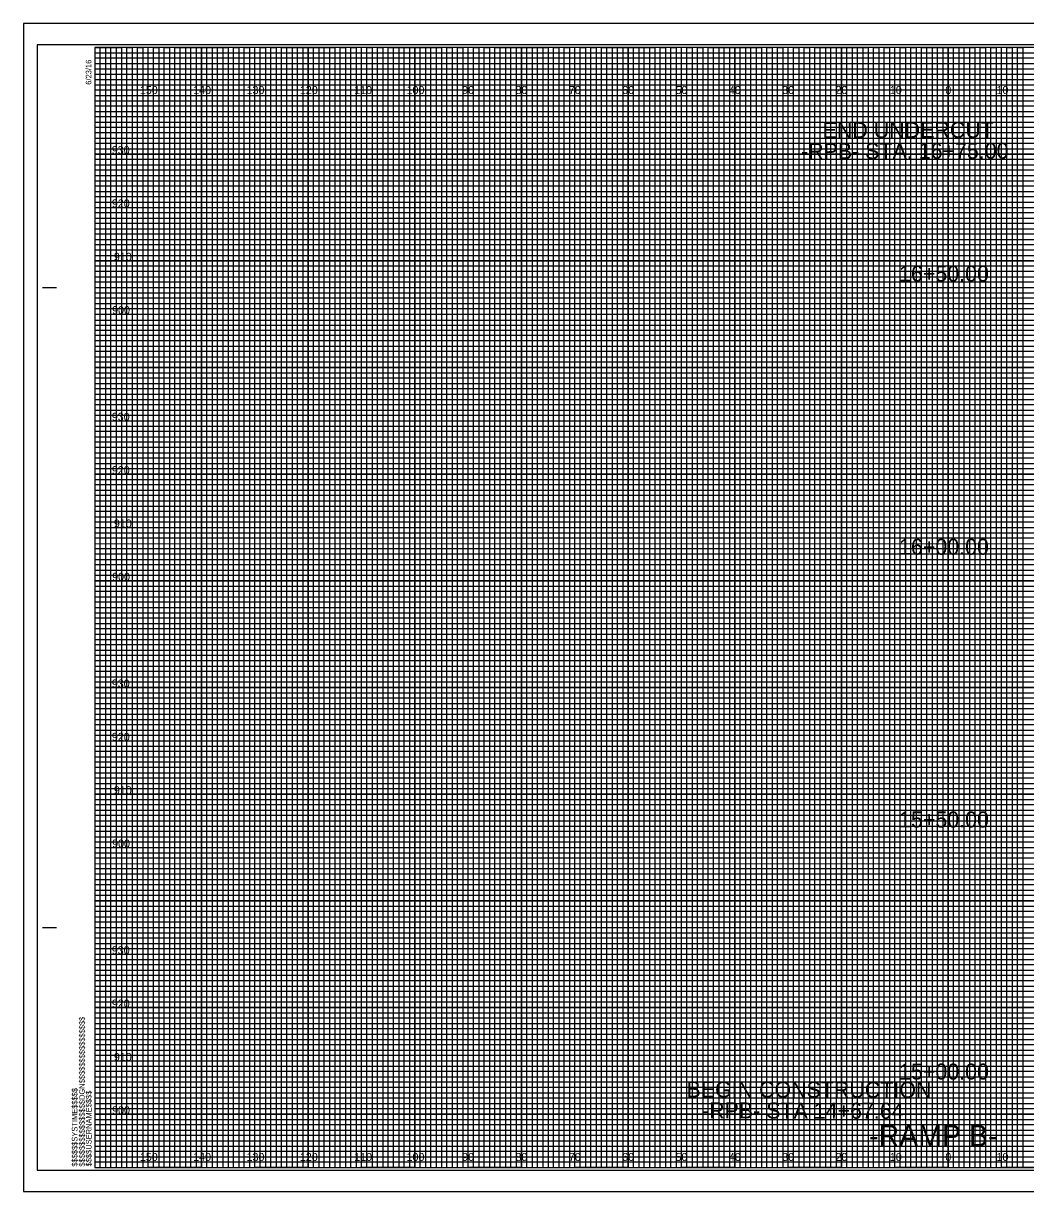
# Model space of a CAD drawing. Extents: x -13 to 323, y -4 to 214.
# Drawn here: x -13.4 to 174.5, y -4.5 to 214.5 of the extents above; entities that cross this region are included whole.
import ezdxf

# ---------------------------------------------------------------- set-up
doc = ezdxf.new("R2010")
doc.units = 0
for name, color, linetype in [('Prop XS Alignment Label', 7, 'Continuous'), ('Prop XS Elevation Labels', 7, 'Continuous'), ('Prop XS Offset Labels', 7, 'Continuous'), ('Prop XS SE Text', 7, 'Continuous'), ('Prop XS Station Labels', 7, 'Continuous'), ('Sheet Cross Section CELL', 7, 'Continuous'), ('Sheet Cross Section Grid Major CELL', 7, 'Continuous'), ('Sheet Cross Section Grid Middle CELL', 7, 'Continuous'), ('Sheet Cross Section Grid Minor 1 CELL', 7, 'Continuous'), ('Sheet Cross Section Grid Minor 2 CELL', 7, 'Continuous'), ('Sheet Cutting Line CELL', 7, 'Continuous'), ('Sheet DOT Grid CELL', 7, 'Continuous'), ('Sheet Plot Border Inside CELL', 7, 'Continuous'), ('Sheet Plot Border Outside CELL', 7, 'Continuous')]:
    doc.layers.add(name, color=color, linetype=linetype)

msp = doc.modelspace()

# ---------------------------------------------------------------- linework, layer by layer
at = {"layer": 'Sheet Cross Section CELL'}
for p, q in [((-9.8, 165), (-7.3, 165)), ((-9.7, 165), (-7.2, 165)), ((-9.8, 45), (-7.3, 45)), ((-9.7, 45), (-7.2, 45)), ((0, 0), (0, 0)), ((0, 0), (0, 0)), ((0, 0), (0, 0)), ((0, 0), (0, 0)), ((0, 0), (0, 0)), ((0, 0), (0, 0)), ((0, 0), (0, 0))]:
    msp.add_line(p, q, dxfattribs=at)
msp.add_lwpolyline([(320, 210), (0, 210), (0, 0), (320, 0)], close=True, dxfattribs=at)
at = {"layer": 'Sheet Cross Section Grid Major CELL'}
for p, q in [((10, 210), (0, 210)), ((10, 0), (10, 210)), ((30, 210), (20, 210)), ((20, 210), (20, 0)), ((30, 0), (30, 210)), ((50, 210), (40, 210)), ((40, 210), (40, 0)), ((50, 0), (50, 210)), ((70, 210), (60, 210)), ((60, 210), (60, 0)), ((70, 0), (70, 210)), ((90, 210), (80, 210)), ((80, 210), (80, 0)), ((90, 0), (90, 210)), ((110, 210), (100, 210)), ((100, 210), (100, 0)), ((110, 0), (110, 210)), ((130, 210), (120, 210)), ((120, 210), (120, 0)), ((130, 0), (130, 210)), ((150, 210), (140, 210)), ((140, 210), (140, 0)), ((150, 0), (150, 210)), ((170, 210), (160, 210)), ((160, 210), (160, 0)), ((170, 0), (170, 210)), ((20, 0), (10, 0)), ((40, 0), (30, 0)), ((60, 0), (50, 0)), ((80, 0), (70, 0)), ((100, 0), (90, 0)), ((120, 0), (110, 0)), ((140, 0), (130, 0)), ((160, 0), (150, 0)), ((180, 0), (170, 0))]:
    msp.add_line(p, q, dxfattribs=at)
for points in [[(0, 200), (320, 200), (320, 190), (0, 190)], [(0, 180), (320, 180), (320, 170), (0, 170)], [(0, 160), (320, 160), (320, 150), (0, 150)], [(0, 140), (320, 140), (320, 130), (0, 130)], [(0, 120), (320, 120), (320, 110), (0, 110)], [(0, 100), (320, 100), (320, 90), (0, 90)], [(0, 80), (320, 80), (320, 70), (0, 70)], [(0, 60), (320, 60), (320, 50), (0, 50)], [(0, 40), (320, 40), (320, 30), (0, 30)], [(0, 20), (320, 20), (320, 10), (0, 10)]]:
    msp.add_lwpolyline(points, dxfattribs=at)
at = {"layer": 'Sheet Cross Section Grid Middle CELL'}
for points in [[(0, 210), (5, 210), (5, 0), (15, 0), (15, 210), (25, 210), (25, 0), (35, 0), (35, 210), (45, 210), (45, 0), (55, 0), (55, 210), (65, 210), (65, 0), (75, 0), (75, 210), (85, 210), (85, 0), (95, 0), (95, 210), (105, 210), (105, 0), (115, 0), (115, 210), (125, 210), (125, 0), (135, 0), (135, 210), (145, 210), (145, 0), (155, 0), (155, 210), (165, 210), (165, 0), (175, 0)], [(0, 205), (275, 205)], [(0, 185), (320, 185), (320, 195), (0, 195)], [(0, 165), (320, 165), (320, 175), (0, 175)], [(0, 145), (320, 145), (320, 155), (0, 155)], [(0, 125), (320, 125), (320, 135), (0, 135)], [(0, 105), (320, 105), (320, 115), (0, 115)], [(0, 85), (320, 85), (320, 95), (0, 95)], [(0, 65), (320, 65), (320, 75), (0, 75)], [(0, 45), (320, 45), (320, 55), (0, 55)], [(0, 25), (320, 25), (320, 35), (0, 35)], [(0, 5), (320, 5), (320, 15), (0, 15)]]:
    msp.add_lwpolyline(points, dxfattribs=at)
at = {"layer": 'Sheet Cross Section Grid Minor 1 CELL'}
for p, q in [((0, 209), (260, 209)), ((260, 207.98), (0, 207.98)), ((0, 207.98), (0, 207)), ((0, 207), (260, 207)), ((260, 205.89), (0, 205.89)), ((0, 205.89), (0, 204)), ((0, 204), (320, 204))]:
    msp.add_line(p, q, dxfattribs=at)
for points in [[(0, 203), (270, 203), (320, 203), (320, 202), (0, 202)], [(0, 201), (320, 201), (320, 199), (0, 199)], [(0, 198), (320, 198), (320, 197), (0, 196.98)], [(0, 196), (320, 196), (320, 194), (0, 194)], [(0, 193), (320, 193), (320, 192), (0, 192)], [(0, 191), (320, 191), (320, 189), (0, 189)], [(0, 188), (320, 188), (320, 187), (0, 187)], [(0, 186), (320, 186), (320, 184), (0, 184)], [(0, 183), (320, 183), (320, 182), (0, 182)], [(0, 181), (320, 181), (320, 179), (0, 179)], [(0, 178), (320, 178), (320, 177), (0, 177)], [(0, 176), (320, 176), (320, 173.95), (320, 173), (320, 172), (0, 172)], [(0, 174), (320, 174), (320, 173), (0, 173)], [(0, 171), (320, 171), (320, 169), (0, 169.03)], [(0, 169.03), (320, 169), (320, 168), (0, 168)], [(0, 167), (320, 167), (320, 166), (0, 166)], [(0, 164), (320, 164), (320, 163), (0, 163)], [(0, 162), (320, 162), (320, 161), (0, 161)], [(-0.07, 158.89), (320, 158.89), (320, 157.88), (-0.07, 157.88)], [(0, 157), (320, 157), (320, 156), (0, 156)], [(0, 154), (320, 154), (320, 153), (0, 153)], [(0, 152), (320, 152), (320, 151), (0, 151)], [(0, 149), (320, 149), (320, 148), (0, 148)], [(0, 147), (320, 147), (320, 146), (0, 146)], [(0, 144), (320, 144), (320, 143), (0, 143)], [(0, 142), (320, 142), (320, 141), (0, 141)], [(0, 139), (320, 139), (319.99, 137.98), (0, 138)], [(0, 137), (320, 137), (320, 136), (0, 136)], [(0, 134), (320, 134), (320, 133), (0, 133)], [(0, 132), (320, 132), (320, 131), (0, 131)], [(0, 129), (320, 129), (320, 128), (0, 128)], [(0, 127), (320, 127), (320, 126), (0, 126)], [(0, 124), (320, 124), (320, 123), (0, 123)], [(0, 122), (320, 122), (320, 121), (0, 121)], [(0, 119), (320, 119), (320, 118), (0, 118)], [(0, 116.99), (320.07, 116.91), (320, 116), (0, 116)], [(0, 114), (320, 114), (320, 113), (0, 113)], [(0, 112), (320, 112), (320, 111), (0, 111)], [(0, 109), (320, 109), (320, 108), (0, 108)], [(0, 107), (320, 107), (320, 106), (0, 106)], [(0, 104), (320, 104), (320, 103), (0, 103)], [(0, 102), (320, 102), (320, 101), (0, 101)], [(0, 99), (320, 99), (320, 98), (0, 98)], [(0, 97), (320, 97), (320, 96), (0, 96)], [(0, 94), (320, 94), (320, 93), (0, 93)], [(0, 92), (320, 92), (320, 91), (0, 91)], [(0, 89), (320, 89), (320, 88), (0, 88)], [(0, 87), (320, 87), (320, 86), (0, 86)], [(0, 84), (320, 84), (320, 83), (0, 83)], [(0, 82), (320, 82), (320, 81), (0, 81)], [(0, 79), (320, 79), (319.99, 77.98), (0, 78)], [(0, 77), (320, 77), (320, 76), (0, 76)], [(0, 74), (320, 74), (320, 73), (0, 73)], [(0, 72), (320, 72), (320, 71), (0, 71)], [(0, 69), (320, 69), (320, 68), (0, 68)], [(0, 67), (320, 67), (320, 66), (0, 66)], [(0, 64), (320, 64), (320, 63), (0, 63)], [(0, 62), (320, 62), (320, 61), (0, 61)], [(0, 59), (320, 59), (320, 58), (0, 58)], [(0, 56.99), (320.07, 56.91), (320, 56), (0, 56)], [(0, 54), (320, 54), (320, 53), (0, 53)], [(0, 52), (320, 52), (320, 51), (0, 51)], [(0, 49), (320, 49), (320, 48), (0, 48)], [(0, 47), (320, 47), (320, 46), (0, 46)], [(0, 44), (320, 44), (320, 43), (0, 43)], [(0, 42), (320, 42), (320, 41), (0, 41)], [(0, 39), (320, 39), (320, 38), (0, 38)], [(0, 37), (320, 37), (320, 36), (0, 36)], [(0, 34), (320, 34), (320, 33), (0, 33)], [(0, 32), (320, 32), (320, 31), (0, 31)], [(0, 29), (320, 29), (320, 28), (0, 28)], [(0, 27), (320, 27), (320, 26), (0, 26)], [(0, 24), (320, 24), (320, 23), (0, 23)], [(0, 22), (320, 22), (320, 21), (0, 21)], [(0, 19), (320, 19), (320, 18), (0, 18)], [(0, 17), (320, 17), (320, 16), (0, 16)], [(0, 14), (320, 14), (320, 13), (0, 13)], [(0, 12), (320, 12), (320, 11), (0, 11)], [(0, 9), (320, 9), (320, 8), (0, 8)], [(0, 7), (320, 7), (320, 6), (0, 6)], [(0, 4), (320, 4), (320, 3), (0, 3)], [(0, 2), (320, 2), (320, 1), (0, 1)]]:
    msp.add_lwpolyline(points, dxfattribs=at)
at = {"layer": 'Sheet Cross Section Grid Minor 2 CELL'}
for points in [[(0, 0), (1, 0), (1, 210), (2, 210), (2, 0)], [(2, 0), (3, 0), (3, 210), (4, 210), (4, 0)], [(5, 0), (6, 0), (6, 210), (7, 210), (7, 0)], [(7, 0), (8, 0), (8, 210), (9, 210), (9, 0)], [(10, 0), (11, 0), (11, 210), (12, 210), (12, 0)], [(12, 0), (13, 0), (13, 210), (14, 210), (14, 0)], [(15, 0), (16, 0), (16, 210), (17, 210), (17, 0)], [(17, 0), (18, 0), (18, 210), (19, 210), (19, 0)], [(20, 0), (21, 0), (21, 210), (22, 210), (22, 0)], [(22, 0), (23, 0), (23, 210), (24, 210), (24, 0)], [(25, 0), (26, 0), (26, 210), (27, 210), (27, 0)], [(27, 0), (28, 0), (28, 210), (29, 210), (29, 0)], [(30, 0), (31, 0), (31, 210), (32, 210), (32, 0)], [(32, 0), (33, 0), (33, 210), (34, 210), (34, 0)], [(35, 0), (36, 0), (36, 210), (37, 210), (37, 0)], [(37, 0), (38, 0), (38, 210), (39, 210), (39, 0)], [(40, 0), (41, 0), (41, 210), (42, 210), (42, 0)], [(42, 0), (43, 0), (43, 210), (44, 210), (44, 0)], [(45, 0), (46, 0), (46, 210), (47, 210), (47, 0)], [(47, 0), (48, 0), (48, 210), (49, 210), (49, 0)], [(50, 0), (51, 0), (51, 210), (52, 210), (52, 0)], [(52, 0), (53, 0), (53, 210), (54, 210), (54, 0)], [(55, 0), (56, 0), (56, 210), (57, 210), (57, 0)], [(57, 0), (58, 0), (58, 210), (59, 210), (59, 0)], [(60, 0), (61, 0), (61, 210), (62, 210), (62, 0)], [(62, 0), (63, 0), (63, 210), (64, 210), (64, 0)], [(65, 0), (66, 0), (66, 210), (67, 210), (67, 0)], [(67, 0), (68, 0), (68, 210), (69, 210), (69, 0)], [(70, 0), (71, 0), (71, 210), (72, 210), (72, 0)], [(72, 0), (73, 0), (73, 210), (74, 210), (74, 0)], [(75, 0), (76, 0), (76, 210), (77, 210), (77, 0)], [(77, 0), (78, 0), (78, 210), (79, 210), (79, 0)], [(80, 0), (81, 0), (81, 210), (82, 210), (82, 0)], [(82, 0), (83, 0), (83, 210), (84, 210), (84, 0)], [(85, 0), (86, 0), (86, 210), (87, 210), (87, 0)], [(87, 0), (88, 0), (88, 210), (89, 210), (89, 0)], [(90, 0), (91, 0), (91, 210), (92, 210), (92, 0)], [(92, 0), (93, 0), (93, 210), (94, 210), (94, 0)], [(95, 0), (96, 0), (96, 210), (97, 210), (97, 0)], [(97, 0), (98, 0), (98, 210), (99, 210), (99, 0)], [(100, 0), (101, 0), (101, 210), (102, 210), (102, 0)], [(102, 0), (103, 0), (103, 210), (104, 210), (104, 0)], [(105, 0), (106, 0), (106, 210), (107, 210), (107, 0)], [(107, 0), (108, 0), (108, 210), (109, 210), (109, 0)], [(110, 0), (111, 0), (111, 210), (112, 210), (112, 0)], [(112, 0), (113, 0), (113, 210), (114, 210), (114, 0)], [(115, 0), (116, 0), (116, 210), (117, 210), (117, 0)], [(117, 0), (118, 0), (118, 210), (119, 210), (119, 0)], [(120, 0), (121, 0), (121, 210), (122, 210), (122, 0)], [(122, 0), (123, 0), (123, 210), (124, 210), (124, 0)], [(125, 0), (126, 0), (126, 210), (127, 210), (127, 0)], [(127, 0), (128, 0), (128, 210), (129, 210), (129, 0)], [(130, 0), (131, 0), (131, 210), (132, 210), (132, 0)], [(132, 0), (133, 0), (133, 210), (134, 210), (134, 0)], [(135, 0), (136, 0), (136, 210), (137, 210), (137, 0)], [(137, 0), (138, 0), (138, 210), (139, 210), (139, 0)], [(140, 0), (141, 0), (141, 210), (142, 210), (142, 0)], [(142, 0), (143, 0), (143, 210), (144, 210), (144, 0)], [(145, 0), (146, 0), (146, 210), (147, 210), (147, 0)], [(147, 0), (148, 0), (148, 210), (149, 210), (149, 0)], [(150, 0), (151, 0), (151, 210), (152, 210), (152, 0)], [(152, 0), (153, 0), (153, 210), (154, 210), (154, 0)], [(155, 0), (156, 0), (156, 210), (157, 210), (157, 0)], [(157, 0), (158, 0), (158, 210), (159, 210), (159, 0)], [(160, 0), (161, 0), (161, 210), (162, 210), (162, 0)], [(162, 0), (163, 0), (163, 210), (164, 210), (164, 0)], [(165, 0), (166, 0), (166, 210), (167, 210), (167, 0)], [(167, 0), (168, 0), (168, 210), (169, 210), (169, 0)], [(170, 0), (171, 0), (171, 210), (172, 210), (172, 0)], [(172, 0), (173, 0), (173, 210), (174, 210), (174, 0)]]:
    msp.add_lwpolyline(points, dxfattribs=at)
at = {"layer": 'Sheet Cutting Line CELL'}
for p, q in [((323.3, 214.5), (-13.4, 214.5)), ((-13.4, 214.5), (-13.4, -4.5)), ((-13.4, -4.5), (323.3, -4.5))]:
    msp.add_line(p, q, dxfattribs=at)
at = {"layer": 'Sheet DOT Grid CELL'}
for p, q in [((10, 0), (10, 210)), ((20, 0), (20, 210)), ((30, 0), (30, 210)), ((40, 0), (40, 210)), ((50, 0), (50, 210)), ((60, 0), (60, 210)), ((70, 0), (70, 210)), ((80, 0), (80, 210)), ((90, 0), (90, 210)), ((100, 0), (100, 210)), ((110, 0), (110, 210)), ((120, 0), (120, 210)), ((130, 0), (130, 210)), ((140, 0), (140, 210)), ((150, 0), (150, 210)), ((160, 0), (160, 210)), ((170, 0), (170, 210)), ((0, 200), (320, 200)), ((0, 190), (320, 190)), ((0, 180), (320, 180)), ((0, 170), (320, 170)), ((0, 160), (320, 160)), ((0, 150), (320, 150)), ((0, 140), (320, 140)), ((0, 130), (320, 130)), ((0, 120), (320, 120)), ((0, 110), (320, 110)), ((0, 100), (320, 100)), ((0, 90), (320, 90)), ((0, 80), (320, 80)), ((0, 70), (320, 70)), ((0, 60), (320, 60)), ((0, 50), (320, 50)), ((0, 40), (320, 40)), ((0, 30), (320, 30)), ((0, 20), (320, 20)), ((0, 10), (320, 10))]:
    msp.add_line(p, q, dxfattribs=at)
at = {"layer": 'Sheet Plot Border Inside CELL'}
msp.add_lwpolyline([(-10.8, -0.5), (322.4, -0.5), (322.4, 210.5), (-10.8, 210.5)], close=True, dxfattribs=at)
at = {"layer": 'Sheet Plot Border Outside CELL'}
msp.add_lwpolyline([(-13.4, -4.5), (323.3, -4.5), (323.3, 214.5), (-13.4, 214.5)], close=True, dxfattribs=at)

# ---------------------------------------------------------------- texts
at = {"layer": 'Prop XS Alignment Label'}
msp.add_text('-RAMP B-', height=4, dxfattribs=at).set_placement((145.14, 4))
at = {"layer": 'Prop XS Elevation Labels'}
for s, p in [('930', (3.18, 190)), ('920', (3.19, 180)), ('910', (3.57, 170)), ('900', (3.24, 160)), ('930', (3.18, 140)), ('920', (3.19, 130)), ('910', (3.57, 120)), ('900', (3.24, 110)), ('930', (3.18, 90)), ('920', (3.19, 80)), ('910', (3.57, 70)), ('900', (3.24, 60)), ('930', (3.18, 40)), ('920', (3.19, 30)), ('910', (3.57, 20)), ('900', (3.24, 10))]:
    msp.add_text(s, height=1.5, dxfattribs=at).set_placement(p)
at = {"layer": 'Prop XS Offset Labels'}
for s, p in [('150', (8.44, 201.25)), ('140', (18.44, 201.25)), ('130', (28.44, 201.25)), ('120', (38.44, 201.25)), ('110', (48.62, 201.25)), ('100', (58.44, 201.25)), ('90', (68.86, 201.25)), ('80', (78.86, 201.25)), ('70', (88.86, 201.25)), ('60', (98.86, 201.25)), ('50', (108.86, 201.25)), ('40', (118.86, 201.25)), ('30', (128.86, 201.25)), ('20', (138.86, 201.25)), ('10', (149.04, 201.25)), ('0', (159.45, 201.25)), ('0', (159.45, 201.25)), ('10', (169.04, 201.25)), ('150', (8.44, 1.25)), ('140', (18.44, 1.25)), ('130', (28.44, 1.25)), ('120', (38.44, 1.25)), ('110', (48.62, 1.25)), ('100', (58.44, 1.25)), ('90', (68.86, 1.25)), ('80', (78.86, 1.25)), ('70', (88.86, 1.25)), ('60', (98.86, 1.25)), ('50', (108.86, 1.25)), ('40', (118.86, 1.25)), ('30', (128.86, 1.25)), ('20', (138.86, 1.25)), ('10', (149.04, 1.25)), ('0', (159.45, 1.25)), ('0', (159.45, 1.25)), ('10', (169.04, 1.25))]:
    msp.add_text(s, height=1.5, dxfattribs=at).set_placement(p)
at = {"layer": 'Prop XS SE Text'}
for s, rotation, p in [('END UNDERCUT', 0.1364, (136.45, 192.98)), ('-RPB- STA. 16+75.00', 0.1364, (132.39, 189.04)), ('BEGIN CONSTRUCTION', 359.8608, (110.92, 13.18)), ('-RPB- STA 14+67.64', 359.8608, (113.82, 9.24))]:
    msp.add_text(s, height=3, rotation=rotation, dxfattribs=at).set_placement(p)
at = {"layer": 'Prop XS Station Labels'}
for s, p in [('16+50.00', (150.77, 166.1)), ('16+00.00', (150.77, 114.89)), ('15+50.00', (150.77, 63.76)), ('15+00.00', (150.77, 16.5))]:
    msp.add_text(s, height=3, dxfattribs=at).set_placement(p)
at = {"layer": 'Sheet Cross Section CELL'}
for s, p in [('6/23/16', (-0.65, 203)), ('$$$$$$$$$$$$$$$$DGN$$$$$$$$$$$$$$$$', (-1.88, 0.18)), ('$$$$$$SYSTIME$$$$$', (-3.26, 0.18)), ('$$$$USERNAME$$$$', (-0.62, 0.23))]:
    msp.add_text(s, height=1.05, rotation=90, dxfattribs=at).set_placement(p)

doc.saveas('drawing.dxf')
